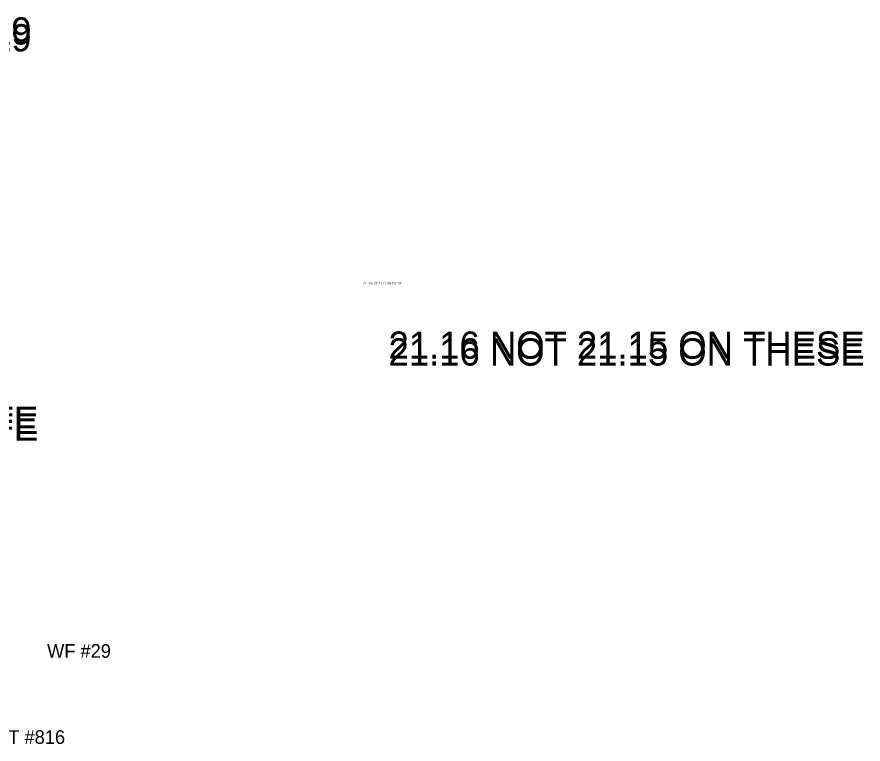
# Model space of a CAD drawing. Extents: x 5447 to 709667, y 4528 to 375472.
# Drawn here: x 706380.9 to 706480.2, y 375094.4 to 375179.8 of the extents above; entities that cross this region are included whole.
import ezdxf

# ---------------------------------------------------------------- set-up
doc = ezdxf.new("R2010")
doc.units = 0
doc.layers.add('SV_SURVEY_NOTES', color=7, linetype='Continuous')

msp = doc.modelspace()

# ---------------------------------------------------------------- texts
at = {"layer": 'SV_SURVEY_NOTES'}
for s, height, p in [('WF #29', 3.2, (706367.633, 375176.55)), ('WF #29', 3.2, (706367.633, 375176.55)), ('WF #29', 3.2, (706367.633, 375176.55)), ('WF #29', 3.2, (706367.633, 375176.55)), ('WF #29', 3.2, (706367.633, 375176.55)), ('WF #29', 3.2, (706367.633, 375176.55)), ('WF #29', 3.2, (706367.633, 375176.55)), ('WF #29', 3.2, (706367.633, 375176.55)), ('WF #29', 3.2, (706367.633, 375175.75)), ('WF #29', 3.2, (706367.633, 375175.75)), ('WF #29', 3.2, (706367.633, 375175.75)), ('21.16 NOT 21.15 ON THESE', 0.25, (706421.563, 375148.385)), ('21.16 NOT 21.15 ON THESE', 3.2, (706424.513, 375139.66)), ('21.16 NOT 21.15 ON THESE', 3.2, (706424.513, 375139.66)), ('21.16 NOT 21.15 ON THESE', 3.2, (706424.513, 375139.66)), ('21.16 NOT 21.15 ON THESE', 3.2, (706424.513, 375139.66)), ('21.16 NOT 21.15 ON THESE', 3.2, (706424.513, 375139.66)), ('21.16 NOT 21.15 ON THESE', 3.2, (706424.513, 375139.66)), ('21.16 NOT 21.15 ON THESE', 3.2, (706424.513, 375139.66)), ('21.16 NOT 21.15 ON THESE', 3.2, (706424.513, 375139.66)), ('21.16 NOT 21.15 ON THESE', 3.2, (706424.513, 375138.86)), ('21.16 NOT 21.15 ON THESE', 3.2, (706424.513, 375138.86)), ('21.16 NOT 21.15 ON THESE', 3.2, (706424.513, 375138.86)), ('15" FE', 3.2, (706370.445, 375130.837)), ('15" FE', 3.2, (706370.445, 375130.837)), ('15" FE', 3.2, (706370.445, 375130.837)), ('15" FE', 3.2, (706370.445, 375130.837)), ('15" FE', 3.2, (706370.445, 375130.837)), ('15" FE', 3.2, (706370.445, 375130.837)), ('15" FE', 3.2, (706370.445, 375130.837)), ('15" FE', 3.2, (706370.445, 375130.837)), ('15" FE', 3.2, (706370.445, 375130.037)), ('15" FE', 3.2, (706370.445, 375130.037)), ('15" FE', 3.2, (706370.445, 375130.037)), ('WF #29', 1.6, (706384.433, 375104.55)), ('SNET #816', 1.6, (706375.479, 375094.438))]:
    msp.add_text(s, height=height, dxfattribs=at).set_placement(p)

doc.saveas('drawing.dxf')
